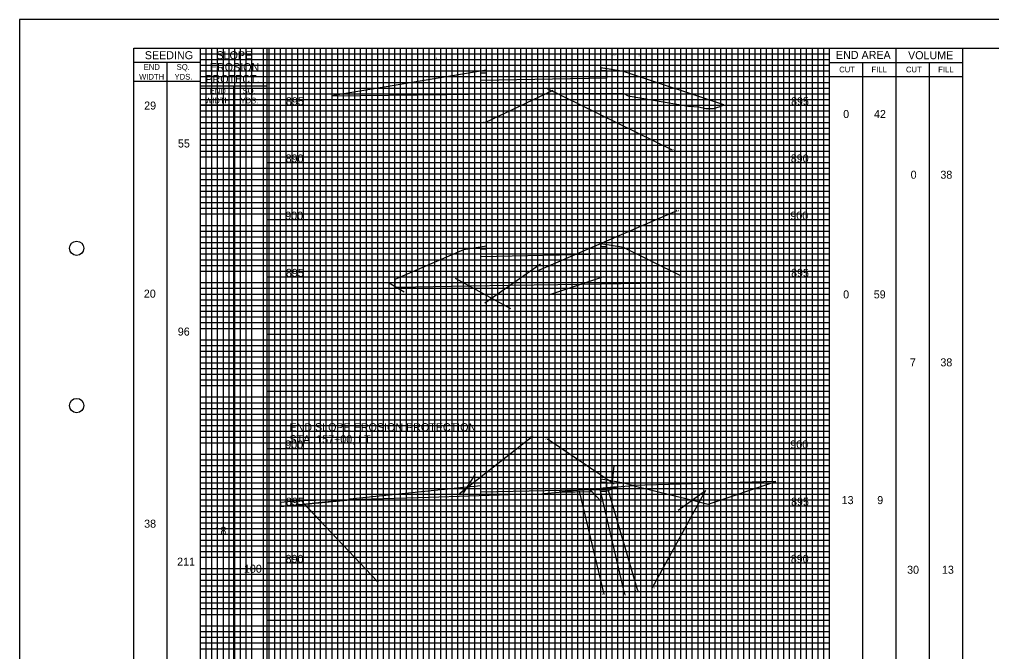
# Model space of a CAD drawing. Extents: x -73 to 160, y -2 to 1877.
# Drawn here: x -10 to 75, y 282.2 to 337.5 of the extents above; entities that cross this region are included whole.
import ezdxf

# ---------------------------------------------------------------- set-up
doc = ezdxf.new("R2010")
doc.units = 0
for name, color, linetype in [('DR_P_Flood_Boundary', 7, 'Continuous'), ('GK_Cells', 7, 'Continuous'), ('RD_X_Fence', 7, 'Continuous'), ('TX_X_5', 7, 'Continuous'), ('UT_P_Water_Cells', 7, 'Continuous'), ('XS_P_Pavt_Surface', 7, 'Continuous'), ('XS_X_Ground_Line', 7, 'Continuous')]:
    doc.layers.add(name, color=color, linetype=linetype)

msp = doc.modelspace()

# ---------------------------------------------------------------- linework, layer by layer
at = {"layer": 'DR_P_Flood_Boundary'}
for p, q in [((15.832, 230), (15.832, 335)), ((20.832, 230), (20.832, 335)), ((25.832, 230), (25.832, 335)), ((30.832, 230), (30.832, 335)), ((35.832, 230), (35.832, 335)), ((40.832, 230), (40.832, 335)), ((45.832, 230), (45.832, 335)), ((50.832, 230), (50.832, 335)), ((55.832, 230), (55.832, 335)), ((5.832, 330), (60.832, 330)), ((11.665, 325), (60.832, 325)), ((11.665, 320), (60.832, 320)), ((11.665, 315), (60.832, 315)), ((11.665, 310), (60.832, 310)), ((11.665, 305), (60.832, 305)), ((11.665, 300), (60.832, 300)), ((5.832, 295), (60.832, 295)), ((11.665, 290), (60.832, 290)), ((11.665, 285), (60.832, 285))]:
    msp.add_line(p, q, dxfattribs=at)
at = {"layer": 'GK_Cells'}
msp.add_lwpolyline([(0, 335), (157.5, 335), (157.5, 230), (0, 230)], close=True, dxfattribs=at)
for centre in [(-5, 317.5), (-5, 303.75)]:
    msp.add_circle(centre, 0.625, dxfattribs=at)
at = {"layer": 'RD_X_Fence'}
for p, q in [((42.832, 332.947), (40.832, 333.28)), ((30.832, 333.08), (17.319, 330.828)), ((30.332, 332.82), (30.832, 332.83)), ((30.332, 332.153), (30.332, 332.82)), ((41.332, 332.373), (30.332, 332.153)), ((40.832, 333.03), (41.332, 333.04)), ((41.332, 333.04), (41.332, 332.373)), ((51.603, 330.023), (42.832, 332.947)), ((36.032, 331.509), (47.08, 326.094)), ((29.332, 330.958), (35.833, 331.004)), ((36.652, 331.304), (30.747, 328.489)), ((38.156, 331.02), (42.332, 331.034)), ((35.426, 315.584), (47.521, 320.791)), ((28.832, 317.357), (22.832, 314.776)), ((30.832, 317.69), (28.832, 317.357)), ((30.332, 317.43), (30.832, 317.44)), ((30.332, 316.763), (30.332, 317.43)), ((42.832, 317.557), (40.832, 317.89)), ((40.832, 317.64), (41.332, 317.65)), ((41.332, 317.65), (41.332, 316.983)), ((47.832, 315.086), (42.832, 317.557)), ((41.332, 316.983), (30.332, 316.763)), ((35.565, 316.112), (30.701, 312.698)), ((22.832, 314.776), (22.832, 314.168)), ((28.099, 314.873), (32.925, 312.222)), ((41.064, 314.996), (36.25, 313.404)), ((47.832, 314.504), (47.832, 315.086)), ((22.331, 314.466), (23.64, 313.687)), ((22.832, 314.168), (22.93, 314.11)), ((22.93, 314.11), (23.092, 314.11)), ((28.464, 296.078), (34.833, 301.061)), ((42.014, 296.894), (36.17, 300.805)), ((41.841, 296.849), (42.015, 298.474)), ((28.856, 296.151), (29.873, 297.757)), ((30.332, 296.183), (30.332, 296.729)), ((40.832, 297.06), (41.332, 297.07)), ((41.332, 297.07), (41.332, 296.553)), ((42.276, 296.644), (43.637, 296.776)), ((43.637, 296.776), (42.832, 296.977)), ((56.143, 297.104), (43.637, 296.776)), ((43.637, 296.776), (48.837, 295.476)), ((50.219, 295.13), (56.143, 297.104)), ((29.332, 295.867), (34.584, 296.03)), ((38.797, 296.353), (30.332, 296.183)), ((34.584, 296.03), (35.52, 296.02)), ((35.52, 296.02), (35.832, 296.052)), ((35.832, 296.052), (37.203, 296.191)), ((38.797, 296.353), (37.203, 296.191)), ((37.203, 296.191), (38.797, 296.353)), ((37.203, 296.191), (40.023, 296.247)), ((39.385, 296.364), (38.797, 296.353)), ((38.928, 296.281), (41.085, 287.272)), ((39.923, 296.375), (39.385, 296.364)), ((41.332, 296.553), (39.918, 296.416)), ((39.924, 296.35), (40.891, 295.342)), ((40.023, 296.247), (39.924, 296.35)), ((40.76, 296.445), (42.911, 287.24)), ((41.332, 296.403), (40.775, 296.382)), ((40.775, 296.382), (40.803, 296.263)), ((40.803, 296.263), (41.332, 296.273)), ((41.332, 296.273), (42.276, 296.644)), ((42.276, 296.644), (41.332, 296.553)), ((41.332, 296.553), (42.276, 296.644)), ((41.332, 296.403), (41.332, 296.553)), ((41.332, 296.553), (41.332, 296.403)), ((41.448, 296.436), (44.047, 287.574)), ((49.999, 296.337), (45.325, 287.808)), ((49.986, 296.293), (47.588, 294.588)), ((12.833, 294.938), (18.905, 295.516)), ((12.833, 294.938), (18.365, 295.504)), ((14.441, 295.421), (12.833, 295.268)), ((14.441, 295.421), (12.833, 295.268)), ((12.833, 295.268), (12.833, 294.938)), ((12.833, 295.268), (12.833, 294.938)), ((18.905, 295.516), (14.441, 295.421)), ((18.365, 295.504), (14.441, 295.421)), ((14.786, 295.27), (21.277, 288.39)), ((48.837, 295.476), (50.219, 295.13))]:
    msp.add_line(p, q, dxfattribs=at)
for points in [[(40.832, 333.28), (40.832, 333.176), (40.832, 333.03)], [(30.832, 332.83), (30.832, 332.976), (30.832, 333.08)], [(17.319, 330.828), (27.374, 330.944), (29.332, 330.958)], [(35.833, 331.004), (36.026, 331.005), (38.156, 331.02)], [(42.332, 331.034), (42.842, 331.036), (43.236, 330.81), (48.513, 329.929), (49.409, 329.872), (50.01, 329.714), (50.684, 329.712), (51.277, 329.89), (51.603, 330.023)], [(30.832, 317.44), (30.832, 317.586), (30.832, 317.69)], [(40.832, 317.89), (40.832, 317.786), (40.832, 317.64)], [(23.092, 314.11), (29.307, 314.209), (32.937, 314.267), (39.159, 314.366), (47.832, 314.504)], [(30.332, 296.729), (29.145, 296.607), (18.901, 295.559)], [(42.832, 296.977), (41.872, 297.137), (40.832, 297.31)], [(40.832, 297.31), (40.832, 297.206), (40.832, 297.06)], [(18.901, 295.553), (18.904, 295.553), (25.79, 295.757), (29.332, 295.867)], [(39.918, 296.416), (39.921, 296.375)], [(39.921, 296.375), (39.923, 296.375), (41.332, 296.403)], [(39.924, 296.35), (39.923, 296.375)], [(18.901, 295.559), (18.901, 295.553)]]:
    msp.add_lwpolyline(points, dxfattribs=at)
at = {"layer": 'TX_X_5'}
msp.add_lwpolyline([(-10, 227.5), (160, 227.5), (160, 337.5), (-10, 337.5)], close=True, dxfattribs=at)
at = {"layer": 'UT_P_Water_Cells'}
for p, q in [((6.332, 230), (6.332, 335)), ((6.832, 230), (6.832, 335)), ((7.332, 230), (7.332, 335)), ((7.832, 230), (7.832, 335)), ((8.332, 230), (8.332, 335)), ((8.832, 230), (8.832, 335)), ((9.332, 230), (9.332, 335)), ((9.832, 230), (9.832, 335)), ((10.332, 230), (10.332, 335)), ((11.332, 230), (11.332, 335)), ((11.832, 230), (11.832, 335)), ((12.332, 230), (12.332, 335)), ((12.832, 230), (12.832, 335)), ((13.332, 230), (13.332, 335)), ((13.832, 230), (13.832, 335)), ((14.332, 230), (14.332, 335)), ((14.832, 230), (14.832, 335)), ((15.332, 230), (15.332, 335)), ((16.332, 230), (16.332, 335)), ((16.832, 230), (16.832, 335)), ((17.332, 230), (17.332, 335)), ((17.832, 230), (17.832, 335)), ((18.332, 230), (18.332, 335)), ((18.832, 230), (18.832, 335)), ((19.332, 230), (19.332, 335)), ((19.832, 230), (19.832, 335)), ((20.332, 230), (20.332, 335)), ((21.332, 230), (21.332, 335)), ((21.832, 230), (21.832, 335)), ((22.332, 230), (22.332, 335)), ((22.832, 230), (22.832, 335)), ((23.332, 230), (23.332, 335)), ((23.832, 230), (23.832, 335)), ((24.332, 230), (24.332, 335)), ((24.832, 230), (24.832, 335)), ((25.332, 230), (25.332, 335)), ((26.332, 230), (26.332, 335)), ((26.832, 230), (26.832, 335)), ((27.332, 230), (27.332, 335)), ((27.832, 230), (27.832, 335)), ((28.332, 230), (28.332, 335)), ((28.832, 230), (28.832, 335)), ((29.332, 230), (29.332, 335)), ((29.832, 230), (29.832, 335)), ((30.332, 230), (30.332, 335)), ((31.332, 230), (31.332, 335)), ((31.832, 230), (31.832, 335)), ((32.332, 230), (32.332, 335)), ((32.832, 230), (32.832, 335)), ((33.332, 230), (33.332, 335)), ((33.832, 230), (33.832, 335)), ((34.332, 230), (34.332, 335)), ((34.832, 230), (34.832, 335)), ((35.332, 230), (35.332, 335)), ((36.332, 230), (36.332, 335)), ((36.832, 230), (36.832, 335)), ((37.332, 230), (37.332, 335)), ((37.832, 230), (37.832, 335)), ((38.332, 230), (38.332, 335)), ((38.832, 230), (38.832, 335)), ((39.332, 230), (39.332, 335)), ((39.832, 230), (39.832, 335)), ((40.332, 230), (40.332, 335)), ((41.332, 230), (41.332, 335)), ((41.832, 230), (41.832, 335)), ((42.332, 230), (42.332, 335)), ((42.832, 230), (42.832, 335)), ((43.332, 230), (43.332, 335)), ((43.832, 230), (43.832, 335)), ((44.332, 230), (44.332, 335)), ((44.832, 230), (44.832, 335)), ((45.332, 230), (45.332, 335)), ((46.332, 230), (46.332, 335)), ((46.832, 230), (46.832, 335)), ((47.332, 230), (47.332, 335)), ((47.832, 230), (47.832, 335)), ((48.332, 230), (48.332, 335)), ((48.832, 230), (48.832, 335)), ((49.332, 230), (49.332, 335)), ((49.832, 230), (49.832, 335)), ((50.332, 230), (50.332, 335)), ((51.332, 230), (51.332, 335)), ((51.832, 230), (51.832, 335)), ((52.332, 230), (52.332, 335)), ((52.832, 230), (52.832, 335)), ((53.332, 230), (53.332, 335)), ((53.832, 230), (53.832, 335)), ((54.332, 230), (54.332, 335)), ((54.832, 230), (54.832, 335)), ((55.332, 230), (55.332, 335)), ((56.332, 230), (56.332, 335)), ((56.832, 230), (56.832, 335)), ((57.332, 230), (57.332, 335)), ((57.832, 230), (57.832, 335)), ((58.332, 230), (58.332, 335)), ((58.832, 230), (58.832, 335)), ((59.332, 230), (59.332, 335)), ((59.832, 230), (59.832, 335)), ((60.332, 230), (60.332, 335)), ((5.832, 334.5), (60.832, 334.5)), ((5.832, 334), (60.832, 334)), ((5.832, 333.5), (60.832, 333.5)), ((5.832, 333), (60.832, 333)), ((5.832, 332.5), (60.832, 332.5)), ((5.832, 332), (60.832, 332)), ((5.832, 331.5), (60.832, 331.5)), ((5.832, 331), (60.832, 331)), ((5.832, 330.5), (60.832, 330.5)), ((5.832, 329.5), (60.832, 329.5)), ((5.832, 329), (60.832, 329)), ((5.832, 328.5), (60.832, 328.5)), ((5.832, 328), (60.832, 328)), ((5.832, 327.5), (60.832, 327.5)), ((5.832, 327), (60.832, 327)), ((5.832, 326.5), (60.832, 326.5)), ((5.832, 326), (60.832, 326)), ((5.832, 325.5), (60.832, 325.5)), ((5.832, 324.5), (60.832, 324.5)), ((5.832, 324), (60.832, 324)), ((5.832, 323.5), (60.832, 323.5)), ((5.832, 323), (60.832, 323)), ((5.832, 322.5), (60.832, 322.5)), ((5.832, 322), (60.832, 322)), ((5.832, 321.5), (60.832, 321.5)), ((5.832, 321), (60.832, 321)), ((5.832, 320.5), (60.832, 320.5)), ((5.832, 319.5), (60.832, 319.5)), ((5.832, 319), (60.832, 319)), ((5.832, 318.5), (60.832, 318.5)), ((5.832, 318), (60.832, 318)), ((5.832, 317.5), (60.832, 317.5)), ((5.832, 317), (60.832, 317)), ((5.832, 316.5), (60.832, 316.5)), ((5.832, 316), (60.832, 316)), ((5.832, 315.5), (60.832, 315.5)), ((5.832, 314.5), (60.832, 314.5)), ((5.832, 314), (60.832, 314)), ((5.832, 313.5), (60.832, 313.5)), ((5.832, 313), (60.832, 313)), ((5.832, 312.5), (60.832, 312.5)), ((5.832, 312), (60.832, 312)), ((5.832, 311.5), (60.832, 311.5)), ((5.832, 311), (60.832, 311)), ((5.832, 310.5), (60.832, 310.5)), ((5.832, 309.5), (60.832, 309.5)), ((5.832, 309), (60.832, 309)), ((5.832, 308.5), (60.832, 308.5)), ((5.832, 308), (60.832, 308)), ((5.832, 307.5), (60.832, 307.5)), ((5.832, 307), (60.832, 307)), ((5.832, 306.5), (60.832, 306.5)), ((5.832, 306), (60.832, 306)), ((5.832, 305.5), (60.832, 305.5)), ((5.832, 304.5), (60.832, 304.5)), ((5.832, 304), (60.832, 304)), ((5.832, 303.5), (60.832, 303.5)), ((5.832, 303), (60.832, 303)), ((5.832, 302.5), (60.832, 302.5)), ((5.832, 302), (60.832, 302)), ((5.832, 301.5), (60.832, 301.5)), ((5.832, 301), (60.832, 301)), ((5.832, 300.5), (60.832, 300.5)), ((5.832, 299.5), (60.832, 299.5)), ((5.832, 299), (60.832, 299)), ((5.832, 298.5), (60.832, 298.5)), ((5.832, 298), (60.832, 298)), ((5.832, 297.5), (60.832, 297.5)), ((5.832, 297), (60.832, 297)), ((5.832, 296.5), (60.832, 296.5)), ((5.832, 296), (60.832, 296)), ((5.832, 295.5), (60.832, 295.5)), ((5.832, 294.5), (60.832, 294.5)), ((5.832, 294), (60.832, 294)), ((5.832, 293.5), (60.832, 293.5)), ((5.832, 293), (60.832, 293)), ((5.832, 292.5), (60.832, 292.5)), ((5.832, 292), (60.832, 292)), ((5.832, 291.5), (60.832, 291.5)), ((5.832, 291), (60.832, 291)), ((5.832, 290.5), (60.832, 290.5)), ((5.832, 289.5), (60.832, 289.5)), ((5.832, 289), (60.832, 289)), ((5.832, 288.5), (60.832, 288.5)), ((5.832, 288), (60.832, 288)), ((5.832, 287.5), (60.832, 287.5)), ((5.832, 287), (60.832, 287)), ((5.832, 286.5), (60.832, 286.5)), ((5.832, 286), (60.832, 286)), ((5.832, 285.5), (60.832, 285.5)), ((5.832, 284.5), (60.832, 284.5)), ((5.832, 284), (60.832, 284)), ((5.832, 283.5), (60.832, 283.5)), ((5.832, 283), (60.832, 283)), ((5.832, 282.5), (60.832, 282.5))]:
    msp.add_line(p, q, dxfattribs=at)
at = {"layer": 'XS_X_Ground_Line'}
for p, q in [((5.832, 230), (5.832, 335)), ((5.832, 230), (5.832, 335)), ((11.665, 230), (11.665, 335)), ((60.832, 230), (60.832, 335)), ((66.667, 230), (66.667, 335)), ((72.5, 230), (72.5, 335)), ((5.832, 333.75), (0, 333.75)), ((2.916, 230), (2.916, 333.75)), ((60.832, 333.75), (72.5, 333.75)), ((63.75, 230), (63.75, 333.75)), ((69.583, 230), (69.583, 333.75)), ((60.832, 332.5), (72.5, 332.5)), ((5.832, 332.083), (0, 332.083)), ((11.665, 331.667), (5.832, 331.667)), ((8.749, 230), (8.749, 331.667)), ((11.665, 330), (5.832, 330))]:
    msp.add_line(p, q, dxfattribs=at)

# ---------------------------------------------------------------- texts
at = {"layer": 'RD_X_Fence'}
for s, p in [('9.9', (26.261, 334.034)), ('2.0', (41.863, 334.331)), ('8.3', (44.122, 334.282)), ('22.8', (30.542, 328.419)), ('41.5', (46.887, 326.024)), ('7.2', (26.595, 322.514)), ('58.9', (47.301, 320.721)), ('6.6', (34.672, 300.991)), ('0.9', (36.005, 300.735)), ('1.1', (21.169, 288.32)), ('0.3', (40.919, 287.202)), ('0.1', (42.769, 287.17)), ('0.2', (43.882, 287.504)), ('11.4', (45.162, 287.738))]:
    msp.add_text(s, height=0.14, dxfattribs=at).set_placement(p)
at = {"layer": 'XS_P_Pavt_Surface'}
for s, p in [('895', (13.303, 330)), ('895', (57.471, 330)), ('29', (0.907, 329.623)), ('0', (62.025, 328.883)), ('42', (64.719, 328.883)), ('55', (3.858, 326.307)), ('890', (13.276, 325)), ('890', (57.443, 325)), ('0', (67.925, 323.578)), ('38', (70.526, 323.578)), ('900', (13.243, 320)), ('900', (57.41, 320)), ('895', (13.303, 315)), ('895', (57.471, 315)), ('20', (0.877, 313.184)), ('0', (62.025, 313.118)), ('59', (64.7, 313.118)), ('96', (3.845, 309.867)), ('7', (67.861, 307.178)), ('38', (70.526, 307.178)), ('END SLOPE EROSION PROTECTION', (13.607, 301.512)), ('STA. 157+00, LT.', (13.607, 300.462)), ('900', (13.243, 300)), ('900', (57.41, 300)), ('13', (61.892, 295.137)), ('9', (65.003, 295.137)), ('895', (13.303, 295)), ('895', (57.471, 295)), ('38', (0.904, 293.075)), ('18', (7.049, 292.456)), ('890', (13.276, 290)), ('890', (57.443, 290)), ('211', (3.787, 289.758)), ('100', (9.631, 289.139)), ('30', (67.616, 289.05)), ('13', (70.664, 289.05))]:
    msp.add_text(s, height=0.7, dxfattribs=at).set_placement(p)
at = {"layer": 'XS_X_Ground_Line'}
for s, height, p in [('SEEDING', 0.7, (0.964, 334.025)), ('SLOPE', 0.7, (7.228, 334.025)), ('END AREA', 0.7, (61.394, 334.047)), ('VOLUME', 0.7, (67.698, 334.025)), ('END', 0.5, (0.87, 333.092)), ('SQ.', 0.5, (3.748, 333.092)), ('EROSION', 0.7, (6.649, 332.983)), ('CUT', 0.5, (61.683, 332.875)), ('FILL', 0.5, (64.502, 332.875)), ('CUT', 0.5, (67.517, 332.875)), ('FILL', 0.5, (70.335, 332.875)), ('WIDTH', 0.5, (0.462, 332.242)), ('YDS.', 0.5, (3.563, 332.242)), ('PROTECT.', 0.7, (6.26, 331.942)), ('END', 0.5, (6.631, 331.008)), ('SQ.', 0.5, (9.51, 331.008)), ('WIDTH', 0.5, (6.224, 330.158)), ('YDS.', 0.5, (9.325, 330.158))]:
    msp.add_text(s, height=height, dxfattribs=at).set_placement(p)

doc.saveas('drawing.dxf')
